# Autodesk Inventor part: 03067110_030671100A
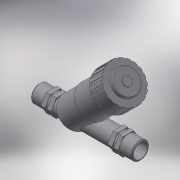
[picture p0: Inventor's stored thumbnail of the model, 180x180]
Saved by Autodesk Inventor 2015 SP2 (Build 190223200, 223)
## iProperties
Created: 2017-05
Part Number: 03067110_030671100A
Material: Generic
Description: PLASSON CHECK VALVE 1"
Document SubType Name: Modeling
Designer: KIM
Mass: 228.741 g
Surface Area: 415.565 cm^2
Volume: 228.741 cm^3
Density: 1 g/cm^3
Appearance: Default
Author: KIM
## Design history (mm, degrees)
derived "03067-03068.ipt"
feature "Solid1::03067-03068.ipt"
tag "TaggingFeature1"
body "Solid1"
other parameters: "d1" = 33.249, "d2" = 36, "d3" = 26.5992, "d6" = 17, "d8" = 1.7, "d12" = 0, "d14" = -8.5, "d15" = 3.4, "d16" = 0, "d17" = 40.068, "d18" = 5.724, "d20" = 50.085, "d21" = 135 deg, "d22" = 52.47, "d23" = 28.62, "d24" = 62.01, "d25" = 14.31, "d29" = 14.31, "d31" = 14.31, "d32" = 47.7, "d34" = 135 deg, "d35" = 2, "d36" = 95.4, "d39" = 59.5, "d40" = 2.12, "d80" = 60.1497, "d81" = 4.24, "d82" = 2.12, "d83" = 24.804, "d84" = 0, "d86" = 360 deg, "d88" = 1.06, "d90" = 1, "d91" = 106, "d92" = 1.431, "R_" = 33.249, "E_" = 36, "A_" = 106, "d13" = 17, "d79" = 62.01
